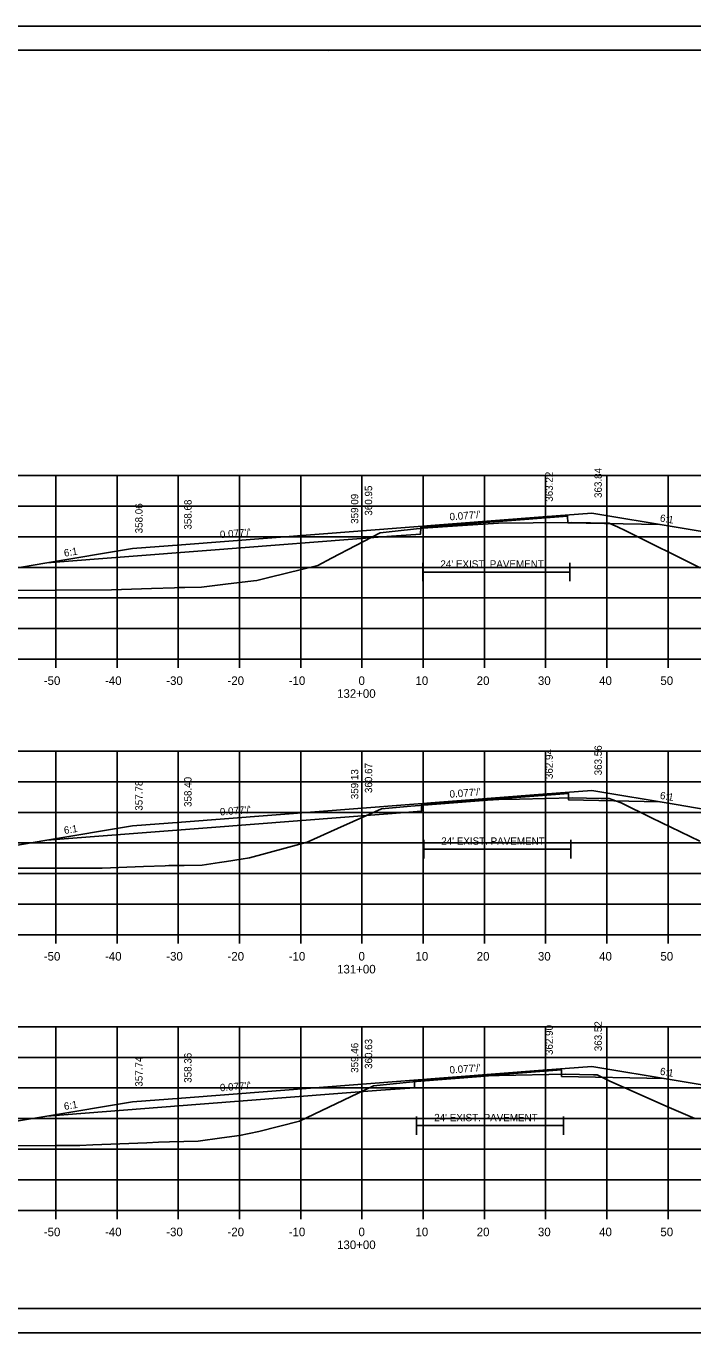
# Model space of a CAD drawing. Extents: x 1374859 to 1376773, y 382242 to 389804.
# Drawn here: x 1376079.7 to 1376188.6, y 385015.1 to 385228.5 of the extents above; entities that cross this region are included whole.
import ezdxf

# ---------------------------------------------------------------- set-up
doc = ezdxf.new("R2010")
doc.units = 0
for name, color, linetype in [('R_Axis', 7, 'Continuous'), ('R_Axis Annot', 7, 'Continuous'), ('R_Border', 7, 'Continuous'), ('R_Border Notes', 7, 'Continuous'), ('R_Exist Surface', 7, 'Continuous'), ('R_Fin Surface', 7, 'Continuous'), ('R_Grid', 7, 'Continuous'), ('R_No Plot', 7, 'Continuous'), ('R_Xsect Elev', 7, 'Continuous'), ('R_Xsect Slope', 7, 'Continuous')]:
    doc.layers.add(name, color=color, linetype=linetype)

msp = doc.modelspace()

# ---------------------------------------------------------------- linework, layer by layer
at = {"layer": 'R_Axis'}
for p, q in [((1375994.57, 385125.11), (1376274.57, 385125.11)), ((1376084.57, 385123.71), (1376084.57, 385125.11)), ((1376094.57, 385123.71), (1376094.57, 385125.11)), ((1376104.57, 385123.71), (1376104.57, 385125.11)), ((1376114.57, 385123.71), (1376114.57, 385125.11)), ((1376124.57, 385123.71), (1376124.57, 385125.11)), ((1376134.57, 385123.71), (1376134.57, 385125.11)), ((1376144.57, 385123.71), (1376144.57, 385125.11)), ((1376154.57, 385123.71), (1376154.57, 385125.11)), ((1376164.57, 385123.71), (1376164.57, 385125.11)), ((1376174.57, 385123.71), (1376174.57, 385125.11)), ((1376184.57, 385123.71), (1376184.57, 385125.11)), ((1375994.57, 385080.11), (1376274.57, 385080.11)), ((1376084.57, 385078.71), (1376084.57, 385080.11)), ((1376094.57, 385078.71), (1376094.57, 385080.11)), ((1376104.57, 385078.71), (1376104.57, 385080.11)), ((1376114.57, 385078.71), (1376114.57, 385080.11)), ((1376124.57, 385078.71), (1376124.57, 385080.11)), ((1376134.57, 385078.71), (1376134.57, 385080.11)), ((1376144.57, 385078.71), (1376144.57, 385080.11)), ((1376154.57, 385078.71), (1376154.57, 385080.11)), ((1376164.57, 385078.71), (1376164.57, 385080.11)), ((1376174.57, 385078.71), (1376174.57, 385080.11)), ((1376184.57, 385078.71), (1376184.57, 385080.11)), ((1375994.57, 385035.11), (1376274.57, 385035.11)), ((1376084.57, 385033.71), (1376084.57, 385035.11)), ((1376094.57, 385033.71), (1376094.57, 385035.11)), ((1376104.57, 385033.71), (1376104.57, 385035.11)), ((1376114.57, 385033.71), (1376114.57, 385035.11)), ((1376124.57, 385033.71), (1376124.57, 385035.11)), ((1376134.57, 385033.71), (1376134.57, 385035.11)), ((1376144.57, 385033.71), (1376144.57, 385035.11)), ((1376154.57, 385033.71), (1376154.57, 385035.11)), ((1376164.57, 385033.71), (1376164.57, 385035.11)), ((1376174.57, 385033.71), (1376174.57, 385035.11)), ((1376184.57, 385033.71), (1376184.57, 385035.11))]:
    msp.add_line(p, q, dxfattribs=at)
at = {"layer": 'R_Border'}
for p, q in [((1375976.57, 385224.57), (1376292.75, 385224.57)), ((1376129.09, 385224.31), (1376129.09, 385224.31)), ((1376129.09, 385224.31), (1376129.09, 385224.31)), ((1376292.75, 385019.11), (1375976.57, 385019.11))]:
    msp.add_line(p, q, dxfattribs=at)
at = {"layer": 'R_Border Notes'}
for points in [[(1376144.51, 385140.84), (1376144.51, 385137.84)], [(1376168.52, 385140.84), (1376168.52, 385137.84)], [(1376144.51, 385139.34), (1376168.52, 385139.34)], [(1376144.65, 385095.6), (1376144.65, 385092.6)], [(1376144.65, 385094.1), (1376168.66, 385094.1)], [(1376168.66, 385095.6), (1376168.66, 385092.6)], [(1376143.5, 385050.47), (1376143.5, 385047.47)], [(1376143.5, 385048.97), (1376167.5, 385048.97)], [(1376167.5, 385050.47), (1376167.5, 385047.47)]]:
    msp.add_lwpolyline(points, dxfattribs=at)
at = {"layer": 'R_Exist Surface'}
for points in [[(1376075.2, 385136.33), (1376084.63, 385136.36), (1376093.66, 385136.43), (1376100.2, 385136.63), (1376103.97, 385136.77), (1376104.67, 385136.8), (1376105.63, 385136.84), (1376108.37, 385136.87), (1376112.27, 385137.36), (1376116.88, 385137.93), (1376117.42, 385137.97), (1376119.56, 385138.52), (1376127.39, 385140.42), (1376129.62, 385141.6), (1376137.52, 385145.76), (1376140.96, 385146.12), (1376144.51, 385146.53), (1376150.99, 385146.93), (1376156.87, 385147.3), (1376162.52, 385147.38), (1376168.76, 385147.43), (1376171.89, 385147.36), (1376174.95, 385147.3), (1376176.03, 385146.86), (1376176.21, 385146.77), (1376177.78, 385146.01), (1376189.81, 385140.03)], [(1376072.45, 385090.98), (1376084.98, 385091), (1376092.13, 385091.01), (1376098.9, 385091.27), (1376102.43, 385091.38), (1376103.01, 385091.41), (1376105.56, 385091.46), (1376108.5, 385091.49), (1376111.32, 385091.91), (1376112.43, 385092.09), (1376114.83, 385092.48), (1376116.18, 385092.69), (1376122.03, 385094.27), (1376125.65, 385095.23), (1376130.57, 385097.45), (1376137.75, 385100.67), (1376142.58, 385101.12), (1376144.65, 385101.3), (1376155.05, 385102.08), (1376156.93, 385102.21), (1376160.3, 385102.29), (1376168.9, 385102.47), (1376173.56, 385102.38), (1376174.97, 385102.35), (1376176.14, 385101.92), (1376176.88, 385101.67), (1376181.86, 385099.24), (1376189.73, 385095.39)], [(1376071.06, 385045.61), (1376084.64, 385045.7), (1376088.5, 385045.72), (1376090.62, 385045.81), (1376099.46, 385046.17), (1376101.34, 385046.25), (1376103.12, 385046.32), (1376107.8, 385046.41), (1376111.7, 385046.99), (1376114.55, 385047.36), (1376117.75, 385048.03), (1376124.39, 385049.69), (1376133.94, 385054.29), (1376136.48, 385055.45), (1376142.88, 385056.11), (1376143.5, 385056.17), (1376154.72, 385057.04), (1376155.85, 385057.13), (1376157, 385057.15), (1376167.8, 385057.39), (1376172.36, 385057.26), (1376172.99, 385057.24), (1376173.54, 385056.96), (1376174.96, 385056.27), (1376184.35, 385052.1), (1376188.94, 385050.11)]]:
    msp.add_lwpolyline(points, dxfattribs=at)
at = {"layer": 'R_Fin Surface'}
for points in [[(1376053.24, 385136.17), (1376059.15, 385134.2), (1376075.09, 385139.51), (1376083.13, 385140.85), (1376097.09, 385143.18), (1376105.09, 385143.79), (1376134.59, 385146.07), (1376164.09, 385148.34), (1376172.09, 385148.95), (1376185.9, 385146.65), (1376194.09, 385145.29), (1376220.61, 385136.44)], [(1376083.13, 385140.85), (1376109.17, 385142.86), (1376138.65, 385145.13), (1376144.15, 385145.55), (1376144.16, 385146.63), (1376168.16, 385148.48), (1376168.17, 385147.4), (1376183.21, 385147.1)], [(1376055.03, 385090.87), (1376060.02, 385089.21), (1376075.09, 385094.23), (1376083.13, 385095.57), (1376097.09, 385097.9), (1376105.09, 385098.51), (1376134.59, 385100.78), (1376164.09, 385103.06), (1376172.09, 385103.67), (1376185.9, 385101.37), (1376194.09, 385100), (1376219.98, 385091.37)], [(1376083.13, 385095.57), (1376109.31, 385097.59), (1376138.79, 385099.86), (1376144.29, 385100.28), (1376144.3, 385101.36), (1376168.3, 385103.21), (1376168.31, 385102.13), (1376183.11, 385101.83)], [(1376056.34, 385045.49), (1376060.17, 385044.21), (1376075.09, 385049.19), (1376083.13, 385050.53), (1376097.09, 385052.85), (1376105.09, 385053.47), (1376134.59, 385055.74), (1376164.09, 385058.01), (1376172.09, 385058.63), (1376185.9, 385056.33), (1376194.09, 385054.96), (1376220.09, 385046.29)], [(1376083.13, 385050.53), (1376108.16, 385052.46), (1376137.64, 385054.73), (1376143.14, 385055.15), (1376143.15, 385056.23), (1376167.15, 385058.08), (1376167.16, 385057), (1376183.87, 385056.66)]]:
    msp.add_lwpolyline(points, dxfattribs=at)
at = {"layer": 'R_Grid'}
for p, q in [((1375994.57, 385155.11), (1376274.57, 385155.11)), ((1376084.57, 385125.11), (1376084.57, 385155.11)), ((1376094.57, 385125.11), (1376094.57, 385155.11)), ((1376104.57, 385125.11), (1376104.57, 385155.11)), ((1376114.57, 385125.11), (1376114.57, 385155.11)), ((1376124.57, 385125.11), (1376124.57, 385155.11)), ((1376134.57, 385125.11), (1376134.57, 385155.11)), ((1376144.57, 385125.11), (1376144.57, 385155.11)), ((1376154.57, 385125.11), (1376154.57, 385155.11)), ((1376164.57, 385125.11), (1376164.57, 385155.11)), ((1376174.57, 385125.11), (1376174.57, 385155.11)), ((1376184.57, 385125.11), (1376184.57, 385155.11)), ((1375994.57, 385150.11), (1376274.57, 385150.11)), ((1375994.57, 385145.11), (1376274.57, 385145.11)), ((1375994.57, 385140.11), (1376274.57, 385140.11)), ((1375994.57, 385135.11), (1376274.57, 385135.11)), ((1375994.57, 385130.11), (1376274.57, 385130.11)), ((1375994.57, 385125.11), (1376274.57, 385125.11)), ((1375994.57, 385110.11), (1376274.57, 385110.11)), ((1376084.57, 385080.11), (1376084.57, 385110.11)), ((1376094.57, 385080.11), (1376094.57, 385110.11)), ((1376104.57, 385080.11), (1376104.57, 385110.11)), ((1376114.57, 385080.11), (1376114.57, 385110.11)), ((1376124.57, 385080.11), (1376124.57, 385110.11)), ((1376134.57, 385080.11), (1376134.57, 385110.11)), ((1376144.57, 385080.11), (1376144.57, 385110.11)), ((1376154.57, 385080.11), (1376154.57, 385110.11)), ((1376164.57, 385080.11), (1376164.57, 385110.11)), ((1376174.57, 385080.11), (1376174.57, 385110.11)), ((1376184.57, 385080.11), (1376184.57, 385110.11)), ((1375994.57, 385105.11), (1376274.57, 385105.11)), ((1375994.57, 385100.11), (1376274.57, 385100.11)), ((1375994.57, 385095.11), (1376274.57, 385095.11)), ((1375994.57, 385090.11), (1376274.57, 385090.11)), ((1375994.57, 385085.11), (1376274.57, 385085.11)), ((1375994.57, 385080.11), (1376274.57, 385080.11)), ((1375994.57, 385065.11), (1376274.57, 385065.11)), ((1376084.57, 385035.11), (1376084.57, 385065.11)), ((1376094.57, 385035.11), (1376094.57, 385065.11)), ((1376104.57, 385035.11), (1376104.57, 385065.11)), ((1376114.57, 385035.11), (1376114.57, 385065.11)), ((1376124.57, 385035.11), (1376124.57, 385065.11)), ((1376134.57, 385035.11), (1376134.57, 385065.11)), ((1376144.57, 385035.11), (1376144.57, 385065.11)), ((1376154.57, 385035.11), (1376154.57, 385065.11)), ((1376164.57, 385035.11), (1376164.57, 385065.11)), ((1376174.57, 385035.11), (1376174.57, 385065.11)), ((1376184.57, 385035.11), (1376184.57, 385065.11)), ((1375994.57, 385060.11), (1376274.57, 385060.11)), ((1375994.57, 385055.11), (1376274.57, 385055.11)), ((1375994.57, 385050.11), (1376274.57, 385050.11)), ((1375994.57, 385045.11), (1376274.57, 385045.11)), ((1375994.57, 385040.11), (1376274.57, 385040.11)), ((1375994.57, 385035.11), (1376274.57, 385035.11))]:
    msp.add_line(p, q, dxfattribs=at)
at = {"layer": 'R_No Plot'}
for p, q in [((1375964.17, 385228.47), (1376297.5, 385228.47)), ((1375964.17, 385015.14), (1376297.5, 385015.14))]:
    msp.add_line(p, q, dxfattribs=at)
for points in [[(1375964.16, 385228.47), (1376297.5, 385228.47), (1376297.5, 385015.13), (1375964.16, 385015.13)], [(1376210.49, 385224.57), (1376210.49, 385214.69), (1376246.22, 385214.69), (1376246.22, 385211.77), (1376269.42, 385211.77), (1376269.42, 385187.44), (1376292.75, 385187.44), (1376292.75, 385019.11), (1375976.57, 385019.11), (1375976.57, 385224.57)]]:
    msp.add_lwpolyline(points, close=True, dxfattribs=at)

# ---------------------------------------------------------------- texts
at = {"layer": 'R_Axis Annot'}
for s, p in [('-50', (1376082.61, 385120.91)), ('-40', (1376092.61, 385120.91)), ('-30', (1376102.61, 385120.91)), ('-20', (1376112.61, 385120.91)), ('-10', (1376122.61, 385120.91)), ('0', (1376134.01, 385120.91)), ('10', (1376143.31, 385120.91)), ('20', (1376153.31, 385120.91)), ('30', (1376163.31, 385120.91)), ('40', (1376173.31, 385120.91)), ('50', (1376183.31, 385120.91)), ('132+00', (1376130.51, 385118.81)), ('-50', (1376082.61, 385075.91)), ('-40', (1376092.61, 385075.91)), ('-30', (1376102.61, 385075.91)), ('-20', (1376112.61, 385075.91)), ('-10', (1376122.61, 385075.91)), ('0', (1376134.01, 385075.91)), ('10', (1376143.31, 385075.91)), ('20', (1376153.31, 385075.91)), ('30', (1376163.31, 385075.91)), ('40', (1376173.31, 385075.91)), ('50', (1376183.31, 385075.91)), ('131+00', (1376130.51, 385073.81)), ('-50', (1376082.61, 385030.91)), ('-40', (1376092.61, 385030.91)), ('-30', (1376102.61, 385030.91)), ('-20', (1376112.61, 385030.91)), ('-10', (1376122.61, 385030.91)), ('0', (1376134.01, 385030.91)), ('10', (1376143.31, 385030.91)), ('20', (1376153.31, 385030.91)), ('30', (1376163.31, 385030.91)), ('40', (1376173.31, 385030.91)), ('50', (1376183.31, 385030.91)), ('130+00', (1376130.51, 385028.81))]:
    msp.add_text(s, height=1.4, dxfattribs=at).set_placement(p)
at = {"layer": 'R_Border Notes'}
for p in [(1376147.38, 385140.06), (1376147.52, 385094.82), (1376146.37, 385049.68)]:
    msp.add_text("24' EXIST. PAVEMENT", height=1.2, rotation=0, dxfattribs=at).set_placement(p)
at = {"layer": 'R_Xsect Elev'}
for s, p in [('363.22', (1376165.74, 385150.82)), ('363.84', (1376173.74, 385151.43)), ('360.95', (1376136.24, 385148.55)), ('359.09', (1376133.97, 385147.21)), ('358.06', (1376098.74, 385145.66)), ('358.68', (1376106.74, 385146.27)), ('363.56', (1376173.74, 385106.15)), ('362.94', (1376165.74, 385105.54)), ('359.13', (1376133.97, 385102.25)), ('360.67', (1376136.24, 385103.26)), ('357.78', (1376098.74, 385100.38)), ('358.40', (1376106.74, 385100.99)), ('363.52', (1376173.74, 385061.11)), ('362.90', (1376165.74, 385060.49)), ('359.46', (1376133.97, 385057.58)), ('360.63', (1376136.24, 385058.22)), ('357.74', (1376098.74, 385055.33)), ('358.36', (1376106.74, 385055.95))]:
    msp.add_text(s, height=1.2, rotation=90, dxfattribs=at).set_placement(p)
at = {"layer": 'R_Xsect Slope'}
for s, rotation, p in [("0.077'/'", 4.4031, (1376148.92, 385147.77)), ('6:1', 350.5358, (1376183.17, 385147.61)), ("0.077'/'", 4.4031, (1376111.42, 385144.88)), ('6:1', 9.4642, (1376086, 385141.84)), ("0.077'/'", 4.4031, (1376148.92, 385102.49)), ('6:1', 350.5358, (1376183.17, 385102.33)), ("0.077'/'", 4.4031, (1376111.42, 385099.6)), ('6:1', 9.4642, (1376086, 385096.56)), ("0.077'/'", 4.4031, (1376148.92, 385057.45)), ('6:1', 350.5358, (1376183.17, 385057.29)), ("0.077'/'", 4.4031, (1376111.42, 385054.56)), ('6:1', 9.4642, (1376086, 385051.51))]:
    msp.add_text(s, height=1.2, rotation=rotation, dxfattribs=at).set_placement(p)

doc.saveas('drawing.dxf')
